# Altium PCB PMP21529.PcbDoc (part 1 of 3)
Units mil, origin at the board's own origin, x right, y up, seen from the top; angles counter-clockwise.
Board outline 4400 x 2200 mil, 4 copper layers (Top Layer, Signal Layer 1, Signal Layer 2, Bottom Layer), stack 41.2 mil thick; 196 components, 92 nets, 502 pads, 268 vias.
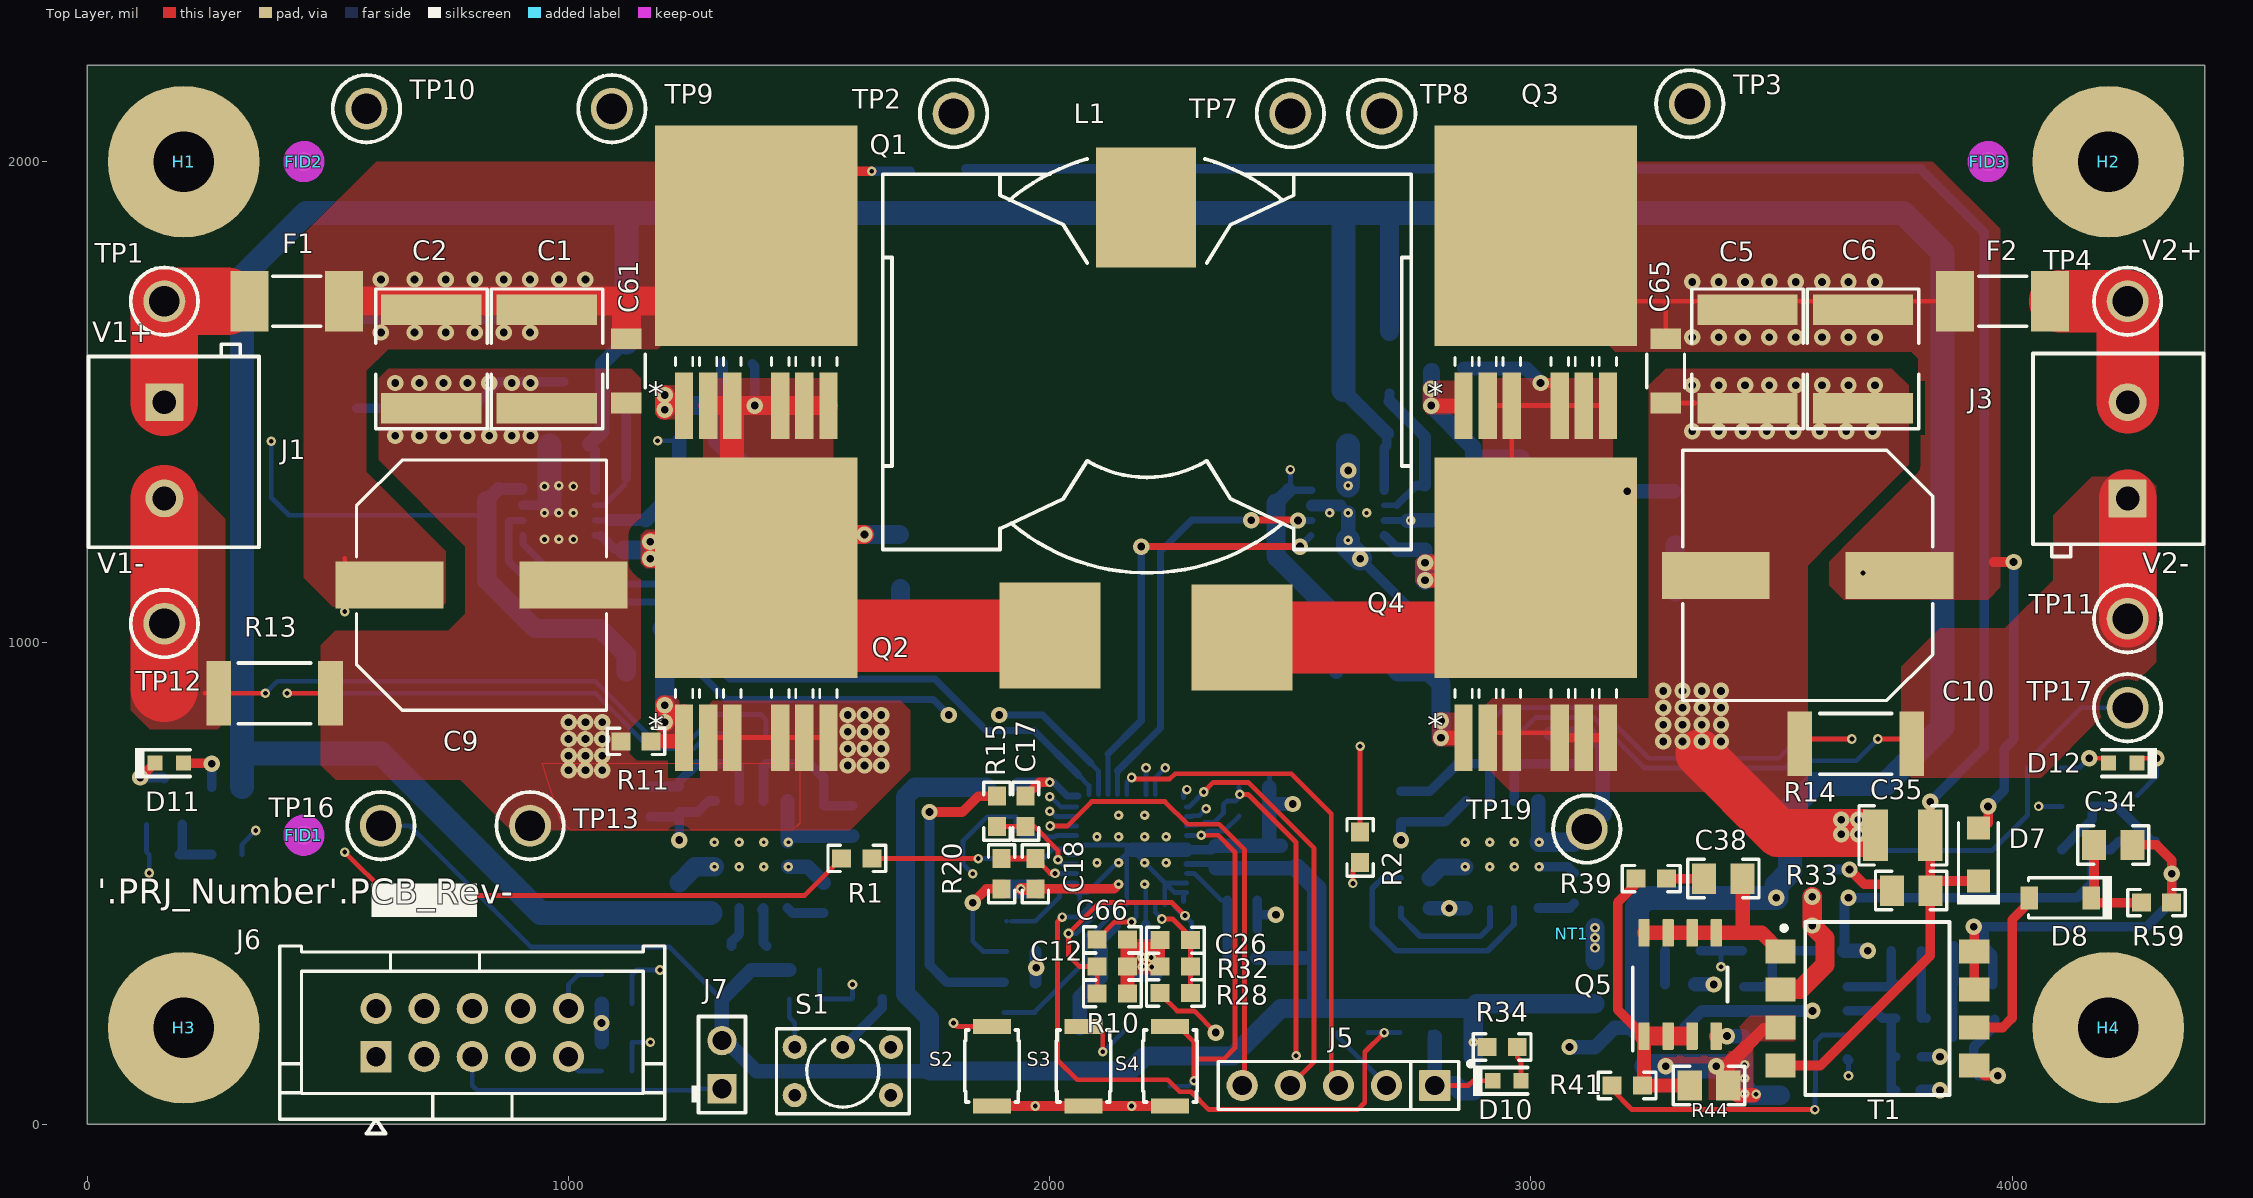
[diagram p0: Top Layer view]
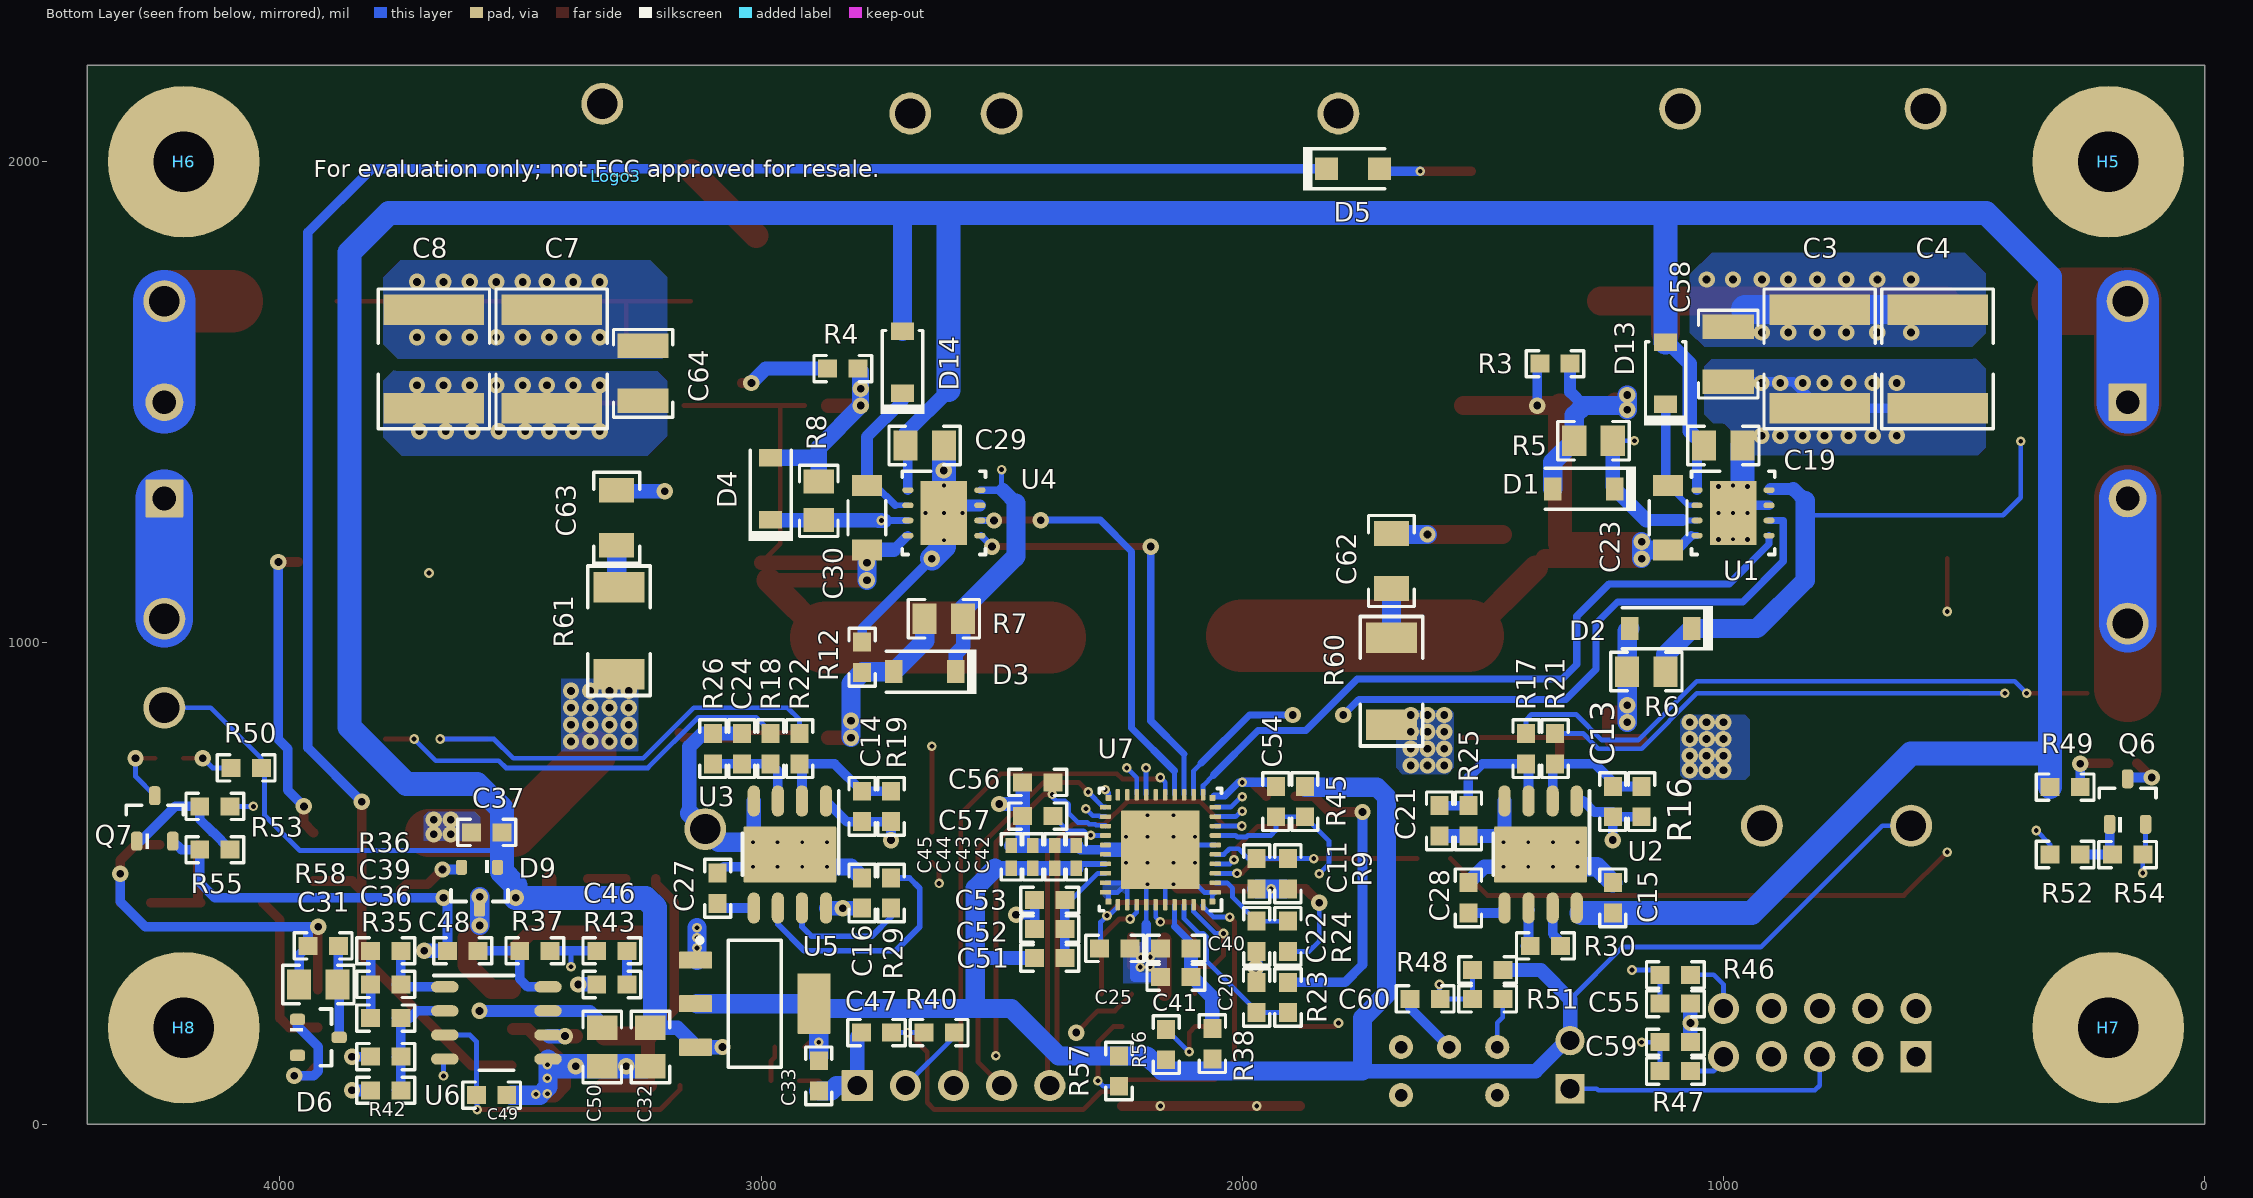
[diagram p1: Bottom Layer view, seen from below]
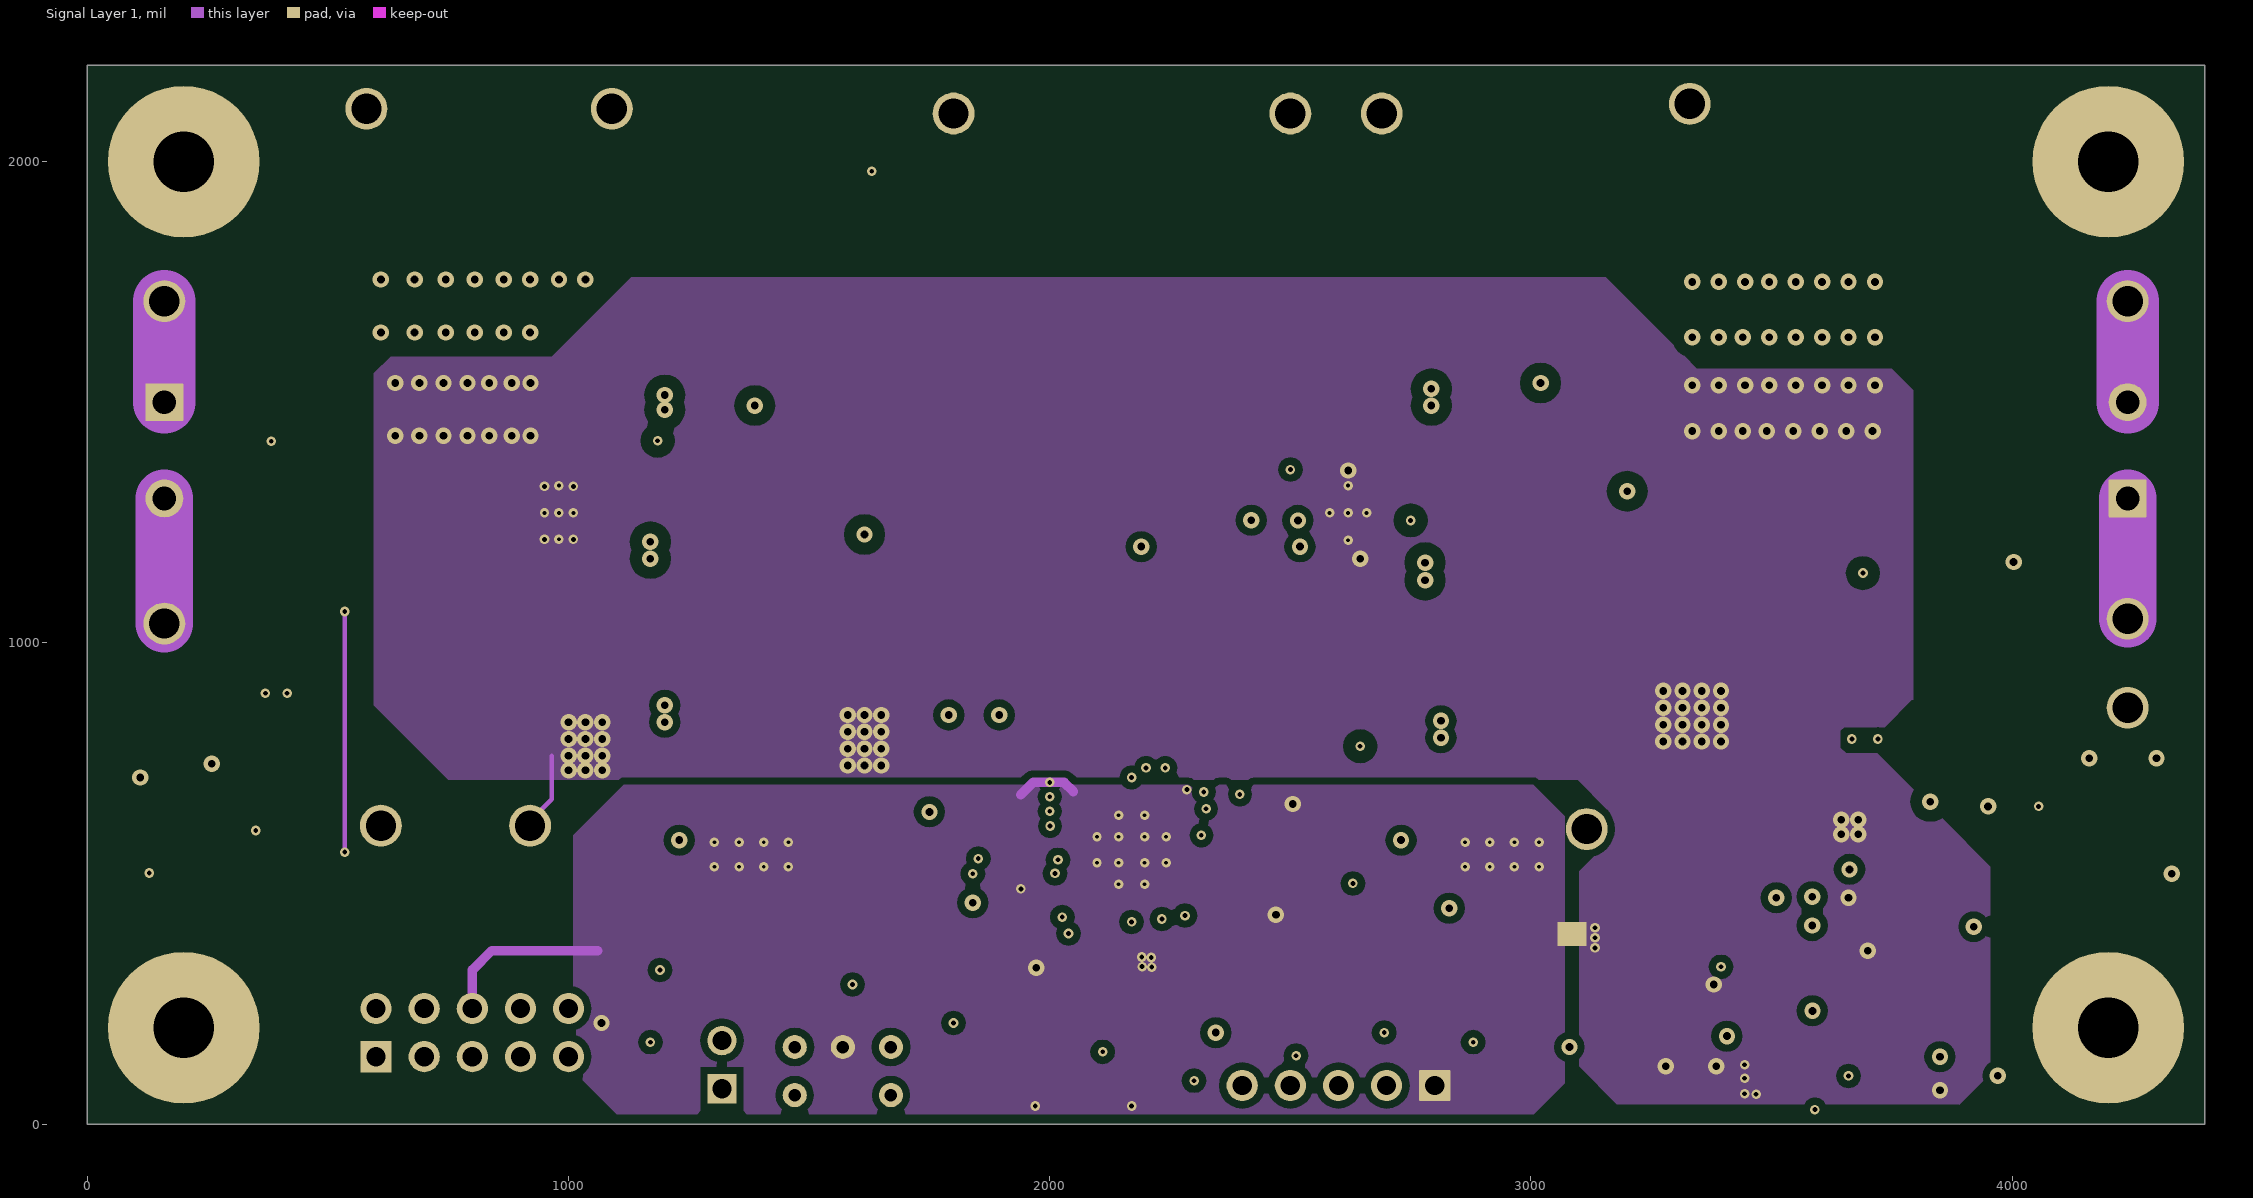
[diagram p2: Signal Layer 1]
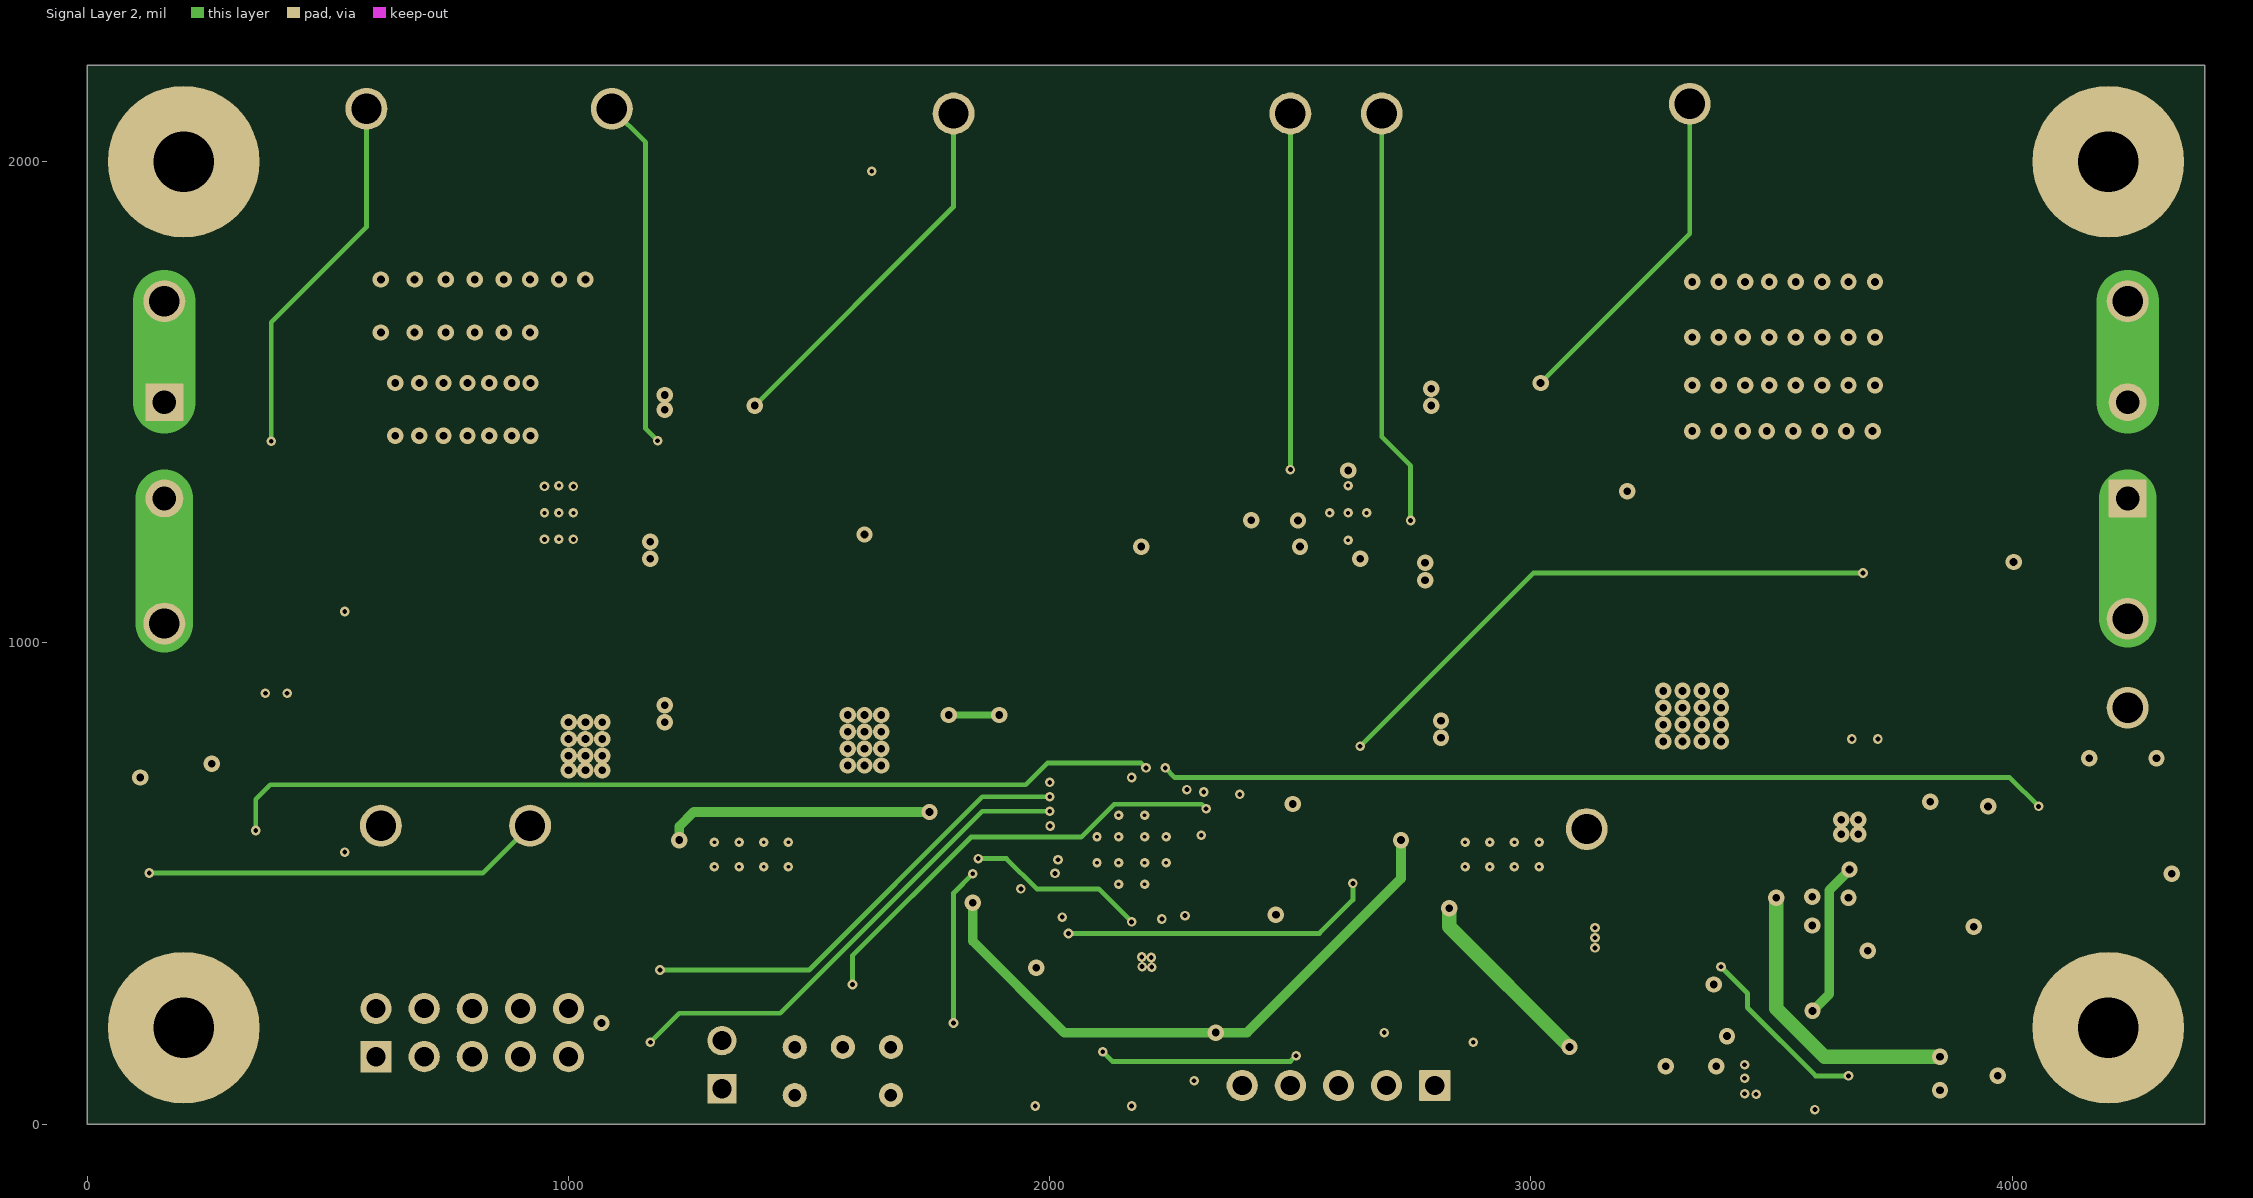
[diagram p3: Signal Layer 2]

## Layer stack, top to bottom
Top Solder: solder mask 0.4, Solder Resist, Dk 3.5
Top Layer: signal copper 2.8
Dielectric1: core 10, FR-4, Dk 4.8
Signal Layer 1: signal copper 2.8
Dielectric 2: core 10, FR-4, Dk 4.8
Signal Layer 2: signal copper 2.8
Dielectric 3: core 10, FR-4, Dk 4.8
Bottom Layer: signal copper 2.8
Bottom Solder: solder mask 0.4, Solder Resist, Dk 3.5

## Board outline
0,0 0,2200 4400,2200 4400,0

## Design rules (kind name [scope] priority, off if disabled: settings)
AcuteAngle [All] p1: minimum=4.50000000000000E+0001 checktracksonly=FALSE
AssemblyTestPointUsage [All] p1: valid=2
BoardOutlineClearance BoardOutlineClearance_MountingHoles [OnCopper and InComponentClass('Mounting Holes')] p1: gap=20 ignorepadtopadclearanceinfootprint=FALSE
BoardOutlineClearance BoardOutlineClearance_Poly [OnCopper and IsPoly] p2: gap=20 ignorepadtopadclearanceinfootprint=FALSE
BoardOutlineClearance [OnCopper and Not InComponentClass('Logo') and not InComponentClass('FiducialMark') and not InRegion(1000,500,4000,800) and not InPoly] p3: gap=20 ignorepadtopadclearanceinfootprint=FALSE
Clearance "1. HVvPGND Objs on Multilayer" [InNetClass('HV') And OnMultiLayer vs Not InNetClass('HV') And OnMultiLayer] p1: gap=25 ignorepadtopadclearanceinfootprint=FALSE except(0: Arc-Text Track-Text SMDPad-Text THPad-Text Via-Text Fill-Text Poly-Text Region-Text Text-Text)
Clearance "2a. HVvPGND Objs on Top" [InNetClass('HV') And OnTopLayer vs Not InNetClass('HV') And (OnTopLayer Or OnMultiLayer)] p2: gap=25 ignorepadtopadclearanceinfootprint=FALSE except(0: Arc-Text Track-Text SMDPad-Text THPad-Text Via-Text Fill-Text Poly-Text Region-Text Text-Text)
Clearance "2b. HVvPGND Objs on Bottom" [InNetClass('HV') And OnBottomLayer vs Not InNetClass('HV') And (OnBottomLayer Or OnMultiLayer)] p3: gap=25 ignorepadtopadclearanceinfootprint=FALSE except(0: Arc-Text Track-Text SMDPad-Text THPad-Text Via-Text Fill-Text Poly-Text Region-Text Text-Text)
Clearance "3a. HVvPGND Objs on Top" [Not InNetClass('HV') And OnTopLayer vs InNetClass('HV') And (OnTopLayer Or OnMultiLayer)] p4: gap=25 ignorepadtopadclearanceinfootprint=FALSE except(0: Arc-Text Track-Text SMDPad-Text THPad-Text Via-Text Fill-Text Poly-Text Region-Text Text-Text)
Clearance "3b. HVvPGND Objs on Bottom_1" [Not InNetClass('HV') And OnBottomLayer vs InNetClass('HV') And (OnBottomLayer Or OnMultiLayer)] p5: gap=25 ignorepadtopadclearanceinfootprint=FALSE except(0: Arc-Text Track-Text SMDPad-Text THPad-Text Via-Text Fill-Text Poly-Text Region-Text Text-Text)
Clearance "4. HVvPGND  Objs on Mid" [InNetClass('HV') And OnMid vs Not InNetClass('HV') And (OnMid Or OnMultiLayer)] p6: gap=25 ignorepadtopadclearanceinfootprint=FALSE except(0: Arc-Text Track-Text SMDPad-Text THPad-Text Via-Text Fill-Text Poly-Text Region-Text Text-Text)
Clearance "5. HVvPGND Objs on Mid" [Not InNetClass('HV') And OnMid vs InNetClass('HV') And (OnMid Or OnMultiLayer)] p7: gap=25 ignorepadtopadclearanceinfootprint=FALSE except(0: Arc-Text Track-Text SMDPad-Text THPad-Text Via-Text Fill-Text Poly-Text Region-Text Text-Text)
Clearance Clearance_Keepouts [((IsTrack Or IsArc) And Not InPoly) And IsFree and IsKeepOut vs ((IsTrack Or IsArc) And Not InPoly) And IsFree and IsKeepOut] p8: gap=0 ignorepadtopadclearanceinfootprint=FALSE
Clearance Clearance_Poly [InPolygon] p9: gap=15 ignorepadtopadclearanceinfootprint=FALSE except(0: Arc-Text Arc-Hole Track-Text Track-Hole SMDPad-Text SMDPad-Hole THPad-Text THPad-Hole Via-Text Via-Hole Fill-Text Fill-Hole Poly-Text Poly-Hole Region-Text Region-Hole Text-Text Text-Hole)
Clearance Clearance_FiducialMark [IsKeepOut and InComponentClass('FiducialMark') vs IsPad and InComponentClass('FiducialMark')] p10: gap=0 ignorepadtopadclearanceinfootprint=FALSE
Clearance [All] p11: gap=7.87 ignorepadtopadclearanceinfootprint=FALSE except(0: Arc-Text Arc-Hole Track-Text Track-Hole SMDPad-Text SMDPad-Hole THPad-Text THPad-Hole Via-Text Via-Hole Fill-Text Fill-Hole Poly-Text Poly-Hole Region-Text Region-Hole Text-Text Text-Hole)
ComponentClearance ComponentClearance_MountingHoles_FiducialMarks [InComponentClass('Mounting Holes') vs InComponentClass('FiducialMark')] p1: gap=50 collisioncheckmode=3 verticalgap=10 showdistances=FALSE
ComponentClearance ComponentClearance_Shunt [InComponentClass('Header') vs InComponentClass('Shunt')] p2: gap=0 collisioncheckmode=3 verticalgap=0 showdistances=FALSE
ComponentClearance ComponentClearance_Logo [InComponentClass('Logo')] p3: gap=0 collisioncheckmode=3 verticalgap=10 showdistances=FALSE
ComponentClearance ComponentClearance_ScrewToNut [(HasFootprint('NY PMS 440 0025 PH')) vs (HasFootprint('Keystone_1902C'))] p4: gap=5 collisioncheckmode=3 verticalgap=10 showdistances=FALSE
ComponentClearance ComponentClearance_MountingHoles [InComponentClass('Mounting Holes')] p5: gap=100 collisioncheckmode=3 verticalgap=100000 showdistances=FALSE
ComponentClearance ComponentClearance_SmallPassives [HasFootprint('0201*') or HasFootprint('0402*') or HasFootprint('0508') or HasFootprint('0603*') or HasFootprint('0612') or HasFootprint('0805*') or HasFootprint('0815*') or HasFootprint('0830*') or HasFootprint('1206*') or HasFootprint('1210*') or HasFootprint('1808*') or HasFootprint('1812*') or HasFootprint('1825*') or HasFootprint('2010*') or HasFootprint('2220*') or HasFootprint('2225*') or HasFootprint('2512*') or HasFootprint('2728*') or HasFootprint('3518*') vs HasFootprint('0201*') or HasFootprint('0402*') or HasFootprint('0508') or HasFootprint('0603*') or HasFootprint('0612') or HasFootprint('0805*') or HasFootprint('0815*') or HasFootprint('0830*') or HasFootprint('1206*') or HasFootprint('1210*') or HasFootprint('1808*') or HasFootprint('1812*') or HasFootprint('1825*') or HasFootprint('2010*') or HasFootprint('2220*') or HasFootprint('2225*') or HasFootprint('2512*') or HasFootprint('2728*') or HasFootprint('3518*')] p6: gap=14.96 collisioncheckmode=3 verticalgap=10 showdistances=FALSE
ComponentClearance ComponentClearance_THtoSMT [IsThruComponent vs IsSMTComponent] p7: gap=30 collisioncheckmode=3 verticalgap=30 showdistances=FALSE
ComponentClearance ComponentClearance_THtoTH [IsThruComponent vs IsThruComponent] p8: gap=30 collisioncheckmode=3 verticalgap=30 showdistances=FALSE
ComponentClearance [All] p9: gap=15 collisioncheckmode=3 verticalgap=10 showdistances=FALSE
DiffPairsRouting [All] p1: maxlimit=100 minlimit=10 mostfreqgap=10 toplayer_minwidth=15 toplayer_maxwidth=15 toplayer_prefwidth=15 midlayer1_minwidth=15 midlayer1_maxwidth=15 midlayer1_prefwidth=15 midlayer2_minwidth=15 midlayer2_maxwidth=15 midlayer2_prefwidth=15 bottomlayer_minwidth=15 bottomlayer_maxwidth=15 bottomlayer_prefwidth=15 maxuncoupledlength=1000
FabricationTestPointUsage TestPointUsage [All] p1: valid=2 allowmultiple=FALSE
FabricationTestpoint Testpoint [All] p1: side=3 testpointundercomponent=TRUE minsize=40 maxsize=100 preferedsize=60 minholesize=0 maxholesize=40 preferedholesize=32 testpointgrid=1 allowsidetop=TRUE allowsidebottom=TRUE usegrid=TRUE gridtolerance=0.01
FanoutControl Fanout_LCC [IsLCC] p1: bgadir=Out bgaviamode=Centered fanoutstyle=Auto fanoutdirection=Alternating viagrid=1 // Fanout_LCC (Default Rule)
FanoutControl Fanout_BGA [IsBGA] p2: bgadir=Out bgaviamode=Centered fanoutstyle=Auto fanoutdirection=Alternating viagrid=1 // Fanout_BGA (Default Rule)
FanoutControl Fanout_Default [All] p4: bgadir=Out bgaviamode=Centered fanoutstyle=Auto fanoutdirection=Alternating viagrid=1 // Fanout_Default (Default Rule)
FanoutControl Fanout_Small [(CompPinCount < 5)] p5: bgadir=Out bgaviamode=Centered fanoutstyle=Auto fanoutdirection=OutThenIn viagrid=1 // Fanout_Small (Default Rule)
HoleSize [All] p1: absolutevalues=TRUE maxlimit=251 minlimit=7.87 maxpercent=80.000 minpercent=20.000
MinimumAnnularRing MinimumAnnularRing_ThermalPadVias [IsVia and InAnyComponent] p1: minimumring=5.91
MinimumAnnularRing [All] p2: minimumring=5
MinimumSolderMaskSliver MinimumSolderMaskSliver_Logo [InComponentClass('Logo') vs InComponentClass('Logo')] p1: minsoldermaskwidth=0.7
MinimumSolderMaskSliver [All] p2: minsoldermaskwidth=3.94
PlaneConnect [All] p1: planeconnectstyle=Relief reliefexpansion=10 reliefentries=4 reliefconductorwidth=10 reliefairgap=10
PolygonConnect PolygonConnect_63 [All vs IsNamedPolygon('BOTTOM_LAYER_PGND_P092')] p1: connectstyle=Direct reliefconductorwidth=10 reliefentries=4 polygonreliefangle="90 Angle" airgapwidth=10
PolygonConnect PolygonConnect_62 [All vs IsNamedPolygon('TOP_LAYER_NETJ1_2_P116')] p2: connectstyle=Direct reliefconductorwidth=10 reliefentries=4 polygonreliefangle="90 Angle" airgapwidth=10
PolygonConnect PolygonConnect_61 [All vs IsNamedPolygon('TOP_LAYER_NETJ3_1_P114')] p3: connectstyle=Direct reliefconductorwidth=10 reliefentries=4 polygonreliefangle="90 Angle" airgapwidth=10
PolygonConnect PolygonConnect_60 [All vs IsNamedPolygon('TOP_LAYER_V2+_P112')] p4: connectstyle=Direct reliefconductorwidth=10 reliefentries=4 polygonreliefangle="90 Angle" airgapwidth=10
PolygonConnect PolygonConnect_59 [All vs IsNamedPolygon('TOP_LAYER_PGND_P110')] p5: connectstyle=Direct reliefconductorwidth=10 reliefentries=4 polygonreliefangle="90 Angle" airgapwidth=10
PolygonConnect PolygonConnect_58 [All vs IsNamedPolygon('BOTTOM_LAYER_PGND_P072')] p6: connectstyle=Direct reliefconductorwidth=10 reliefentries=4 polygonreliefangle="90 Angle" airgapwidth=10
PolygonConnect PolygonConnect_57 [All vs IsNamedPolygon('TOP_LAYER_V1+_P108')] p7: connectstyle=Direct reliefconductorwidth=10 reliefentries=4 polygonreliefangle="90 Angle" airgapwidth=10
PolygonConnect PolygonConnect_56 [All vs IsNamedPolygon('TOP_LAYER_PGND_P106')] p8: connectstyle=Direct reliefconductorwidth=10 reliefentries=4 polygonreliefangle="90 Angle" airgapwidth=10
PolygonConnect PolygonConnect_55 [All vs IsNamedPolygon('TOP_LAYER_AGND_P104')] p9: connectstyle=Direct reliefconductorwidth=10 reliefentries=4 polygonreliefangle="90 Angle" airgapwidth=10
PolygonConnect PolygonConnect_54 [All vs IsNamedPolygon('BOTTOM_LAYER_AGND_P102')] p10: connectstyle=Direct reliefconductorwidth=10 reliefentries=4 polygonreliefangle="90 Angle" airgapwidth=10
PolygonConnect PolygonConnect_53 [All vs IsNamedPolygon('BOTTOM_LAYER_AGND_P100')] p11: connectstyle=Direct reliefconductorwidth=10 reliefentries=4 polygonreliefangle="90 Angle" airgapwidth=10
PolygonConnect PolygonConnect_52 [All vs IsNamedPolygon('BOTTOM_LAYER_AGND_P098')] p12: connectstyle=Direct reliefconductorwidth=10 reliefentries=4 polygonreliefangle="90 Angle" airgapwidth=10
PolygonConnect PolygonConnect_51 [All vs IsNamedPolygon('BOTTOM_LAYER_PGND_P096')] p13: connectstyle=Direct reliefconductorwidth=10 reliefentries=4 polygonreliefangle="90 Angle" airgapwidth=10
PolygonConnect PolygonConnect_50 [All vs IsNamedPolygon('TOP_LAYER_PGND_P094')] p14: connectstyle=Direct reliefconductorwidth=10 reliefentries=4 polygonreliefangle="90 Angle" airgapwidth=10
PolygonConnect PolygonConnect_49 [All vs IsNamedPolygon('BOTTOM_LAYER_NETC5_2_P092')] p15: connectstyle=Direct reliefconductorwidth=10 reliefentries=4 polygonreliefangle="90 Angle" airgapwidth=10
PolygonConnect PolygonConnect_48 [All vs IsNamedPolygon('BOTTOM_LAYER_V2+_P090')] p16: connectstyle=Direct reliefconductorwidth=10 reliefentries=4 polygonreliefangle="90 Angle" airgapwidth=10
PolygonConnect PolygonConnect_47 [All vs IsNamedPolygon('TOP_LAYER_NETC5_2_P088')] p17: connectstyle=Direct reliefconductorwidth=10 reliefentries=4 polygonreliefangle="90 Angle" airgapwidth=10
PolygonConnect PolygonConnect_46 [All vs IsNamedPolygon('TOP_LAYER_V2+_P086')] p18: connectstyle=Direct reliefconductorwidth=10 reliefentries=4 polygonreliefangle="90 Angle" airgapwidth=10
PolygonConnect PolygonConnect_45 [All vs IsNamedPolygon('TOP_LAYER_PGND_P082')] p19: connectstyle=Direct reliefconductorwidth=10 reliefentries=4 polygonreliefangle="90 Angle" airgapwidth=10
PolygonConnect PolygonConnect_44 [All vs IsNamedPolygon('TOP_LAYER_NETC1_2_P080')] p20: connectstyle=Direct reliefconductorwidth=10 reliefentries=4 polygonreliefangle="90 Angle" airgapwidth=10
PolygonConnect PolygonConnect_43 [All vs IsNamedPolygon('TOP_LAYER_NETC1_2_P080')] p21: thpad.connectstyle=Relief thpad.reliefconductorwidth=10 thpad.reliefentries=4 thpad.polygonreliefangle="90 Angle" thpad.airgapwidth=10 smdpad.connectstyle=Direct smdpad.reliefconductorwidth=10 smdpad.reliefentries=4 smdpad.polygonreliefangle="90 Angle" smdpad.airgapwidth=10 via.connectstyle=Relief via.reliefconductorwidth=10 via.reliefentries=4 via.polygonreliefangle="90 Angle" via.airgapwidth=10
PolygonConnect PolygonConnect_42 [All vs IsNamedPolygon('BOTTOM_LAYER_PGND_P078')] p22: connectstyle=Direct reliefconductorwidth=10 reliefentries=4 polygonreliefangle="90 Angle" airgapwidth=10
PolygonConnect PolygonConnect_41 [All vs IsNamedPolygon('BOTTOM_LAYER_PGND_P076')] p23: connectstyle=Direct reliefconductorwidth=10 reliefentries=4 polygonreliefangle="90 Angle" airgapwidth=10
PolygonConnect PolygonConnect_40 [All vs IsNamedPolygon('TOP_LAYER_PGND_P074')] p24: connectstyle=Direct reliefconductorwidth=10 reliefentries=4 polygonreliefangle="90 Angle" airgapwidth=10
PolygonConnect PolygonConnect_39 [All vs IsNamedPolygon('BOTTOM_LAYER_NETC1_2_P072')] p25: connectstyle=Direct reliefconductorwidth=10 reliefentries=4 polygonreliefangle="90 Angle" airgapwidth=10
PolygonConnect PolygonConnect_38 [All vs IsNamedPolygon('BOTTOM_LAYER_V1+_P070')] p26: connectstyle=Direct reliefconductorwidth=10 reliefentries=4 polygonreliefangle="90 Angle" airgapwidth=10
PolygonConnect PolygonConnect_37 [All vs IsNamedPolygon('TOP_LAYER_NETC1_2_P068')] p27: connectstyle=Direct reliefconductorwidth=10 reliefentries=4 polygonreliefangle="90 Angle" airgapwidth=10
PolygonConnect PolygonConnect_36 [All vs IsNamedPolygon('TOP_LAYER_V1+_P064')] p28: connectstyle=Direct reliefconductorwidth=10 reliefentries=4 polygonreliefangle="90 Angle" airgapwidth=10
PolygonConnect PolygonConnect_35 [All vs IsNamedPolygon('TOP_LAYER_SW1_P062')] p29: connectstyle=Direct reliefconductorwidth=10 reliefentries=4 polygonreliefangle="90 Angle" airgapwidth=10
PolygonConnect PolygonConnect_34 [All vs IsNamedPolygon('TOP_LAYER_NETD2_2_P060')] p30: connectstyle=Direct reliefconductorwidth=10 reliefentries=4 polygonreliefangle="90 Angle" airgapwidth=10
PolygonConnect PolygonConnect_33 [All vs IsNamedPolygon('TOP_LAYER_NETD1_2_P056')] p31: connectstyle=Direct reliefconductorwidth=10 reliefentries=4 polygonreliefangle="90 Angle" airgapwidth=10
PolygonConnect PolygonConnect_32 [All vs IsNamedPolygon('SIGNAL_LAYER_1_PGND_P054')] p32: connectstyle=Direct reliefconductorwidth=10 reliefentries=4 polygonreliefangle="90 Angle" airgapwidth=10
PolygonConnect PolygonConnect_31 [All vs IsNamedPolygon('TOP_LAYER_NETC5_2_P050')] p33: connectstyle=Direct reliefconductorwidth=10 reliefentries=4 polygonreliefangle="90 Angle" airgapwidth=10
PolygonConnect PolygonConnect_30 [All vs IsNamedPolygon('TOP_LAYER_V2+_P048')] p34: connectstyle=Direct reliefconductorwidth=10 reliefentries=4 polygonreliefangle="90 Angle" airgapwidth=10
PolygonConnect PolygonConnect_29 [All vs IsNamedPolygon('TOP_LAYER_NETC1_2_P046')] p35: connectstyle=Direct reliefconductorwidth=10 reliefentries=4 polygonreliefangle="90 Angle" airgapwidth=10
PolygonConnect PolygonConnect_28 [All vs IsNamedPolygon('TOP_LAYER_PGND_P044')] p36: connectstyle=Direct reliefconductorwidth=10 reliefentries=4 polygonreliefangle="90 Angle" airgapwidth=10
PolygonConnect PolygonConnect_27 [All vs IsNamedPolygon('TOP_LAYER_V1+_P042')] p37: connectstyle=Direct reliefconductorwidth=10 reliefentries=4 polygonreliefangle="90 Angle" airgapwidth=10
PolygonConnect PolygonConnect_26 [All vs IsNamedPolygon('TOP_LAYER_NETD3_2_P040')] p38: connectstyle=Direct reliefconductorwidth=10 reliefentries=4 polygonreliefangle="90 Angle" airgapwidth=10
PolygonConnect PolygonConnect_25 [All vs IsNamedPolygon('TOP_LAYER_SW2_P036')] p39: connectstyle=Direct reliefconductorwidth=10 reliefentries=4 polygonreliefangle="90 Angle" airgapwidth=10
PolygonConnect PolygonConnect_24 [All vs IsNamedPolygon('TOP_LAYER_NETD4_2_P034')] p40: connectstyle=Direct reliefconductorwidth=10 reliefentries=4 polygonreliefangle="90 Angle" airgapwidth=10
PolygonConnect PolygonConnect_23 [All vs IsNamedPolygon('BOTTOM_LAYER_AGND_P032')] p41: thpad.connectstyle=Direct thpad.reliefconductorwidth=10 thpad.reliefentries=4 thpad.polygonreliefangle="90 Angle" thpad.airgapwidth=10 smdpad.connectstyle=Direct smdpad.reliefconductorwidth=10 smdpad.reliefentries=4 smdpad.polygonreliefangle="90 Angle" smdpad.airgapwidth=10 via.connectstyle=Relief via.reliefconductorwidth=10 via.reliefentries=4 via.polygonreliefangle="90 Angle" via.airgapwidth=10
PolygonConnect PolygonConnect_22 [All vs IsNamedPolygon('BOTTOM_LAYER_AGND_P032')] p42: connectstyle=Direct reliefconductorwidth=10 reliefentries=4 polygonreliefangle="90 Angle" airgapwidth=10
PolygonConnect PolygonConnect_21 [All vs IsNamedPolygon('BOTTOM_LAYER_AGND_P032')] p43: connectstyle=Direct reliefconductorwidth=10 reliefentries=4 polygonreliefangle="90 Angle" airgapwidth=10
PolygonConnect PolygonConnect_20 [All vs IsNamedPolygon('BOTTOM_LAYER_AGND_P030')] p44: connectstyle=Direct reliefconductorwidth=10 reliefentries=4 polygonreliefangle="90 Angle" airgapwidth=10
PolygonConnect PolygonConnect_19 [All vs IsNamedPolygon('BOTTOM_LAYER_AGND_P028')] p45: connectstyle=Direct reliefconductorwidth=10 reliefentries=4 polygonreliefangle="90 Angle" airgapwidth=10
PolygonConnect PolygonConnect_18 [All vs IsNamedPolygon('BOTTOM_LAYER_AGND_P028')] p46: connectstyle=Direct reliefconductorwidth=10 reliefentries=4 polygonreliefangle="90 Angle" airgapwidth=10
PolygonConnect PolygonConnect_17 [All vs IsNamedPolygon('BOTTOM_LAYER_AGND_P028')] p47: connectstyle=Direct reliefconductorwidth=10 reliefentries=4 polygonreliefangle="90 Angle" airgapwidth=10
PolygonConnect PolygonConnect_16 [All vs IsNamedPolygon('BOTTOM_LAYER_AGND_P028')] p48: connectstyle=Direct reliefconductorwidth=10 reliefentries=4 polygonreliefangle="90 Angle" airgapwidth=10
PolygonConnect PolygonConnect_15 [All vs IsNamedPolygon('BOTTOM_LAYER_AGND_P028')] p49: thpad.connectstyle=Direct thpad.reliefconductorwidth=10 thpad.reliefentries=4 thpad.polygonreliefangle="90 Angle" thpad.airgapwidth=10 smdpad.connectstyle=Direct smdpad.reliefconductorwidth=10 smdpad.reliefentries=4 smdpad.polygonreliefangle="90 Angle" smdpad.airgapwidth=10 via.connectstyle=Relief via.reliefconductorwidth=10 via.reliefentries=4 via.polygonreliefangle="90 Angle" via.airgapwidth=10
PolygonConnect PolygonConnect_14 [All vs IsNamedPolygon('BOTTOM_LAYER_AGND_P028')] p50: connectstyle=Direct reliefconductorwidth=10 reliefentries=4 polygonreliefangle="90 Angle" airgapwidth=10
PolygonConnect PolygonConnect_13 [All vs IsNamedPolygon('BOTTOM_LAYER_AGND_P028')] p51: connectstyle=Direct reliefconductorwidth=10 reliefentries=4 polygonreliefangle="90 Angle" airgapwidth=10
PolygonConnect PolygonConnect_12 [All vs IsNamedPolygon('BOTTOM_LAYER_AGND_P028')] p52: connectstyle=Direct reliefconductorwidth=10 reliefentries=4 polygonreliefangle="90 Angle" airgapwidth=10
PolygonConnect PolygonConnect_11 [All vs IsNamedPolygon('SIGNAL_LAYER_1_PGND_P022')] p53: connectstyle=Direct reliefconductorwidth=10 reliefentries=4 polygonreliefangle="90 Angle" airgapwidth=10
PolygonConnect PolygonConnect_10 [All vs IsNamedPolygon('BOTTOM_LAYER_PGND_P020')] p54: connectstyle=Direct reliefconductorwidth=10 reliefentries=4 polygonreliefangle="90 Angle" airgapwidth=10
PolygonConnect PolygonConnect_9 [All vs IsNamedPolygon('BOTTOM_LAYER_PGND_P018')] p55: connectstyle=Direct reliefconductorwidth=10 reliefentries=4 polygonreliefangle="90 Angle" airgapwidth=10
PolygonConnect PolygonConnect_8 [All vs IsNamedPolygon('SIGNAL_LAYER_1_AGND_P002')] p56: connectstyle=Direct reliefconductorwidth=10 reliefentries=4 polygonreliefangle="90 Angle" airgapwidth=10
PolygonConnect PolygonConnect_7 [All vs IsNamedPolygon('SIGNAL_LAYER_1_PGND_P000')] p57: connectstyle=Direct reliefconductorwidth=10 reliefentries=4 polygonreliefangle="90 Angle" airgapwidth=10
PolygonConnect PolygonConnect_6 [All vs IsNamedPolygon('TOP_LAYER_PGND_P016')] p58: connectstyle=Direct reliefconductorwidth=10 reliefentries=4 polygonreliefangle="90 Angle" airgapwidth=10
PolygonConnect PolygonConnect_5 [All vs IsNamedPolygon('TOP_LAYER_PGND_P012')] p59: connectstyle=Direct reliefconductorwidth=10 reliefentries=4 polygonreliefangle="90 Angle" airgapwidth=10
PolygonConnect PolygonConnect_4 [All vs IsNamedPolygon('TOP_LAYER_PGND_P010')] p60: connectstyle=Direct reliefconductorwidth=10 reliefentries=4 polygonreliefangle="90 Angle" airgapwidth=10
PolygonConnect PolygonConnect_3 [All vs IsNamedPolygon('SIGNAL_LAYER_1_PGND_P004')] p61: connectstyle=Direct reliefconductorwidth=10 reliefentries=4 polygonreliefangle="90 Angle" airgapwidth=10
PolygonConnect PolygonConnect_2 [All vs IsNamedPolygon('TOP_LAYER_SW1_P008')] p62: connectstyle=Direct reliefconductorwidth=10 reliefentries=4 polygonreliefangle="90 Angle" airgapwidth=10
PolygonConnect PolygonConnect_1 [All vs IsNamedPolygon('TOP_LAYER_SW2_P006')] p63: connectstyle=Direct reliefconductorwidth=10 reliefentries=4 polygonreliefangle="90 Angle" airgapwidth=10
PolygonConnect [All] p64: connectstyle=Relief reliefconductorwidth=10 reliefentries=4 polygonreliefangle="90 Angle" airgapwidth=10
RoutingVias ThermalPadVias [IsVia and InAnyComponent] p1: holewidth=7.87 width=19.68 viastyle="Through Hole" minholewidth=7.87 minwidth=19.68 maxholewidth=12.99 maxwidth=23.62
RoutingVias [All] p2: holewidth=16 width=34 viastyle="Through Hole" minholewidth=7.87 minwidth=20 maxholewidth=40 maxwidth=65
SilkToBoardRegionClearance [Not ((IsComment or IsDesignator) And (Hide <> 'False')) and not InRegion(1000,500,4000,800)] p1:
SilkToSilkClearance SilkToSilkClearance_Pb-FreeLogo [(HasFootprint('Pb-Free_Overlay_Medium') OR HasFootprint('Pb-Free_Overlay_Small')) vs (HasFootprint('Pb-Free_Overlay_Medium') OR HasFootprint('Pb-Free_Overlay_Small'))] p1: silktosilkclearance=0
SilkToSilkClearance [All] p2: silktosilkclearance=1
SilkToSolderMaskClearance SilkToComponentPadClearance [(IsPad or IsFill or IsRegion) and InAnycomponent] p1: minsilkscreentomaskgap=5 clearancetoexposedcopper=TRUE
SilkToSolderMaskClearance "Silk to Solder Mask Opening" [All] p2: minsilkscreentomaskgap=1 clearancetoexposedcopper=FALSE
SolderMaskExpansion [All] p1: expansion=1.97
Width [All] p1: maxlimit=200 minlimit=6 preferedwidth=10 checkconnectedcopper=TRUE
15 further rules are at their usual default settings.

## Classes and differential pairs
component class AssemblyNote: ZZ2 ZZ3 ZZ4
component class FiducialMark: FID1 FID2 FID3
component class PMP21529_Hardware: FID1 FID2 FID3 H1 H2 H3 H4 H5 H6 H7 H8 Logo3 ZZ2 ZZ3 ZZ4
component class "Mounting Holes": H1 H2 H3 H4
component class Header: J5
component class PMP21529_Sheet1: C1 C2 C3 C4 C5 C6 C7 C8 C9 C10 C13 C14 C15 C16 C17 C18 C19 C20 C21 C22 C23 C24 C26 C27 C28 C29 C30 C58 C61 C62 C63 C64 C65 D1 D2 D3 D4 D13 D14 F1 F2 J1 J3 L1 Q1 Q2 Q3 Q4 R3 R4 R5 R6 R7 R8 R11 R12 R13 R14 R15 R16 R17 R18 R19 R20 R21 R22 R23 R24 R25 R26 R28 R29 R30 R32 R60 R61 TP1 TP2 TP3 TP4 TP7 TP8 TP9 TP10 TP11 TP12 TP13 U1 U2 U3 U4
component class PMP21529_Sheet2: C11 C12 C25 C31 C32 C33 C34 C35 C36 C37 C38 C39 C40 C41 C42 C43 C44 C45 C46 C47 C48 C49 C50 C51 C52 C53 C54 C55 C56 C57 C59 C60 C66 D5 D6 D7 D8 D9 D10 D11 D12 J5 J6 J7 NT1 Q5 Q6 Q7 R1 R2 R9 R10 R33 R34 R35 R36 R37 R38 R39 R40 R41 R42 R43 R44 R45 R46 R47 R48 R49 R50 R51 R52 R53 R54 R55 R56 R57 R58 R59 S1 S2 S3 S4 T1 TP16 TP17 TP19 U5 U6 U7
net class HV: H1 H2 NetC35_1 NetC38_1 NetD1_2 NetD4_2 NetF2_1 SW1 SW2 V1+ V2+

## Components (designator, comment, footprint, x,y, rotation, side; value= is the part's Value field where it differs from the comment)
C1 "22201C106MAT2A" 2220_280 955,1590 r270 top value=10uF
C2 "22201C106MAT2A" 2220_280 715,1590 r270 top value=10uF
C3 "22201C106MAT2A" 2220_280 800,1590 r270 bottom value=10uF
C4 "22201C106MAT2A" 2220_280 555,1590 r270 bottom value=10uF
C5 "22201C106MAT2A" 2220_280 3450,1590 r270 top value=10uF
C6 "22201C106MAT2A" 2220_280 3690,1590 r270 top value=10uF
C7 "22201C106MAT2A" 2220_280 3435,1590 r270 bottom value=10uF
C8 "22201C106MAT2A" 2220_280 3680,1590 r270 bottom value=10uF
C9 "EMVA101ATR101MKE0S" CAPSMT_62_KE0 819,1120 r0 top value=100uF
C10 "EMVA101ATR101MKE0S" CAPSMT_62_KE0 3575,1140 r180 top value=100uF
C11 "GRM188R71E682KA01D" 0603 1970,520 r270 bottom value=6800pF
C12 "GRM188R71E682KA01D" 0603 2130,327 r0 top value=6800pF
C13 "Capacitor" 0603 1230,670 r270 bottom value=22pF
C14 "Capacitor" 0603 2790,660 r270 bottom value=22pF
C15 "Capacitor" 0603 1230,470 r90 bottom value=0.1uF
C16 "Capacitor" 0603 2790,480 r90 bottom value=0.1uF
C17 "Capacitor" 0603 1950,650 r90 top value=330pF
C18 "Capacitor" 0603 1970,520 r270 top value=330pF
C19 "GRM21BR71C475KA73L" 0805_HV 1000,1410 r180 bottom value=4.7uF
C20 "Capacitor" 0603 1970,263 r90 bottom value=2.2uF
C21 "Capacitor" 0603 1590,630 r270 bottom value=22pF
C22 "Capacitor" 0603 1970,390 r270 bottom value=2.2uF
C23 "C3216X7S2A225K160AB" 1206_180 1115,1260 r270 bottom value=2.2uF
C24 "Capacitor" 0603 3040,780 r90 bottom value=22pF
C25 "C0603C221K5RACTU" 0603 2265,365 r180 bottom value=220pF
C26 "Capacitor" 0603 2261,382 r180 top value=0.01uF
C27 "Capacitor" 0603 3090,490 r90 bottom value=22pF
C28 "Capacitor" 0603 1530,470 r90 bottom value=22pF
C29 "GRM21BR71C475KA73L" 0805_HV 2660,1410 r180 bottom value=4.7uF
C30 "C3216X7S2A225K160AB" 1206_180 2780,1260 r270 bottom value=2.2uF
C31 "Capacitor" 0805_HV 3920,290 r0 bottom value=2.2uF
C32 "Capacitor" 0805_HV 3230,160 r270 bottom value=10uF
C33 "Capacitor" 0603 2880,100 r270 bottom value=10uF
C34 "Capacitor" 0805_HV 4210,580 r0 top value=2.2uF
C35 "GRM32ER72A225KA35L" 1210_270 3773,600 r180 top value=2.2uF
C36 "Capacitor" 0603 3780,220 r0 bottom value=0.01uF
C37 "EMK107B7105KA-T" 0603 3570,606 r0 bottom value=1uF
C38 "Capacitor" 0805_HV 3400,510 r180 top value=47pF
C39 "Capacitor" 0603 3780,290 r180 bottom value=47pF
C40 "Capacitor" 0603 2138,365 r0 bottom value=0.01uF
C41 "Capacitor" 0603 2138,305 r0 bottom value=1uF
C42 "GRM155R71E104KE14D" 0402 2345,555 r90 bottom value=0.1uF
C43 "GRM155R71E104KE14D" 0402 2390,555 r90 bottom value=0.1uF
C44 "GRM155R71E104KE14D" 0402 2435,555 r90 bottom value=0.1uF
C45 "GRM155R70J105KA12D" 0402 2480,555 r90 bottom value=1uF
C46 "Capacitor" 0603 3310,360 r0 bottom value=330pF
C47 "Capacitor" 0603 2760,190 r0 bottom value=0.01uF
C48 "Capacitor" 0603 3620,360 r0 bottom value=0.1uF
C49 "Capacitor" 0603 3560,60 r180 bottom value=220pF
C50 "Capacitor" 0805_HV 3330,160 r270 bottom value=4.7uF
C51 "Capacitor" 0603 2400,345 r0 bottom value=2.2uF
C52 "EMK107B7105KA-T" 0603 2400,405 r0 bottom value=1uF
C53 "C0603H103J3GACTU" 0603 2400,465 r0 bottom value=0.01uF
C54 "EMK107BB7225MA-T" 0603 1930,670 r90 bottom value=2.2uF
C55 "Capacitor" 0603 1100,250 r180 bottom value=33pF
C56 "EMK107BB7225MA-T" 0603 2425,710 r0 bottom value=2.2uF
C57 "EMK107BB7225MA-T" 0603 2425,640 r0 bottom value=2.2uF
C58 "GRM32DC72A475KE01L" 1210_220 990,1600 r270 bottom value=4.7uF
C59 "Capacitor" 0603 1100,170 r180 bottom value=33pF
C60 "Capacitor" 0603 1620,260 r0 bottom value=0.01uF
C61 "C3216X7R2A105K160AA" 1206_180 1120,1565 r270 top value=1uF
C62 "GRM3195C2A562JA01D" 1206 1690,1170 r270 bottom value=5600pF
C63 "GRM3195C2A562JA01D" 1206 3300,1260 r270 bottom value=5600pF
C64 "GRM32DC72A475KE01L" 1210_220 3245,1560 r270 bottom value=4.7uF
C65 "C3216X7R2A105K160AA" 1206_180 3280,1565 r270 top value=1uF
C66 "C0603C221K5RACTU" 0603 2130,383 r0 top value=220pF
D1 "MBR0540T1G" SOD-123 1290,1320 r0 bottom value=40V
D2 "MBR0540T1G" SOD-123 1130,1030 r0 bottom value=40V
D3 "MBR0540T1G" SOD-123 2660,940 r0 bottom value=40V
D4 "MBR0540T1G" SOD-123 2980,1320 r90 bottom value=40V
D5 "PMEG10010ELRX" SOD-123W 1770,1985 r180 bottom value=100V
D6 "DIODE_A1C3" SOT-23L 3920,180 r180 bottom value=100V
D7 "PMEG10010ELRX" SOD-123W 3930,560 r90 top value=100V
D8 "MBR140SFT1G" SOD-123FL 4100,470 r180 top value=40V
D9 "DIODE_A3C1_A3C2" SOT-23L 3585,490 r270 bottom value=70V
D10 "LTST-C190GKT" LED_LTST-C190 2950,90 r180 top value=Green
D11 "LTST-C190GKT" LED_LTST-C190 170,750 r180 top value=Green
D12 "LTST-C190GKT" LED_LTST-C190 4230,750 r0 top value=Green
D13 "MBR1H100SFT3G" SOD-123FL 1120,1560 r90 bottom value=100V
D14 "MBR1H100SFT3G" SOD-123FL 2706,1583 r90 bottom value=100V
F1 "SSQ 15" FUSE_SSQ 435,1710 r180 top
F2 "SSQ 15" FUSE_SSQ 3980,1710 r180 top
FID1 "Fiducial" Fiducial10-20 450,600 r0 top
FID2 "Fiducial" Fiducial10-20 450,2000 r0 top
FID3 "Fiducial" Fiducial10-20 3950,2000 r0 top
H1 "NY PMS 440 0025 PH" "NY PMS 440 0025 PH" 200,2000 r0 top locked
H2 "NY PMS 440 0025 PH" "NY PMS 440 0025 PH" 4200,2000 r0 top locked
H3 "NY PMS 440 0025 PH" "NY PMS 440 0025 PH" 200,200 r0 top locked
H4 "NY PMS 440 0025 PH" "NY PMS 440 0025 PH" 4200,200 r0 top locked
H5 "1902C" Keystone_1902C 200,2000 r180 bottom locked
H6 "1902C" Keystone_1902C 4200,2000 r180 bottom locked
H7 "1902C" Keystone_1902C 200,200 r180 bottom locked
H8 "1902C" Keystone_1902C 4200,200 r180 bottom locked
J1 "Receptacle_2x1" On-Shore_ED120_2DS 160,1400 r270 top
J3 "Receptacle_2x1" On-Shore_ED120_2DS 4240,1400 r90 top
J5 "HTSW-105-07-G-S" Samtec_HTSW-105-07-G-S 2600,80 r180 top
J6 "Header_5x2" CONN_5103308-1 800,190 r0 top
J7 "HTSW-102-09-G-S" Samtec_HTSW-102-09-x-S 1318.77,123.39 r90 top
L1 "SER2918H-153KL" SER2918H 2200,1580 r90 top value=15uH
Logo3 "FCC disclaimer" FCC_disclaimer 3302,1970 r180 bottom
NT1 "Net-Tie" Net-Tie_50milWide_30milLong 3085,395 r180 top net-tie
Q1 "IPB180N08S402ATMA1" DDPAK-7 1390,1840 r0 top value=80V
Q2 "IPB180N08S402ATMA1" DDPAK-7 1390,1150 r0 top value=80V
Q3 "IPB180N08S402ATMA1" DDPAK-7 3010,1840 r0 top value=80V
Q4 "IPB180N08S402ATMA1" DDPAK-7 3010,1150 r0 top value=80V
Q5 "FDS2670" SOIC-8 3310,290 r90 top value=200V
Q6 "MMBT3904" SOT-23 160,670 r90 bottom value="40 V"
Q7 "MMBT3904" SOT-23 4260,635 r90 bottom value="40 V"
R1 "RT0603BRD0741K2L" 0603 1599,552 r180 top value=41.2k
R2 "RT0603BRD0741K2L" 0603 2645,575 r90 top value=41.2k
R3 "CRCW060310K0FKEA" 0603 1350,1580 r0 bottom value=10.0k
R4 "CRCW060310K0FKEA" 0603 2830,1570 r0 bottom value=10.0k
R5 "CRCW08055R11FKEA" 0805_HV 1270,1420 r0 bottom value=5.11
R6 "CRCW08055R11FKEA" 0805_HV 1160,940 r0 bottom value=5.11
R7 "CRCW08055R11FKEA" 0805_HV 2620,1050 r180 bottom value=5.11
R8 "CRCW08055R11FKEA" 0805_HV 2880,1295 r270 bottom value=5.11
R9 "RT0603BRD071K1L" 0603 1905,520 r90 bottom value=1.10k
R10 "RT0603BRD071K1L" 0603 2130,271 r180 top value=1.10k
R11 "CRCW060310K0FKEA" 0603 1140,795 r0 top value=10.0k
R12 "CRCW060310K0FKEA" 0603 2790,970 r270 bottom value=10.0k
R13 "Resistor" 2512 389,895 r0 top value=0.002
R14 "Resistor" 2512 3675,790 r0 top value=0.002
R15 "Resistor" 0603 1890,650 r270 top value=120
R16 "RC0603FR-07120KL" 0603 1170,670 r90 bottom value=120k
R17 "Resistor" 0603 1410,780 r270 bottom value=1.00k
R18 "Resistor" 0603 2980,780 r270 bottom value=1.00k
R19 "RC0603FR-07120KL" 0603 2730,660 r270 bottom value=120k
R20 "Resistor" 0603 1900,520 r90 top value=120
R21 "Resistor" 0603 1350,780 r270 bottom value=1.00k
R22 "Resistor" 0603 2920,780 r270 bottom value=1.00k
R23 "Resistor" 0603 1905,263 r270 bottom value=1.0k
R24 "Resistor" 0603 1905,390 r90 bottom value=1.0k
R25 "RC0603FR-07120KL" 0603 1530,630 r90 bottom value=120k
R26 "RC0603FR-07120KL" 0603 3100,780 r270 bottom value=120k
R28 "RT0603DRE072K03L" 0603 2261,272 r180 top value=2.03k
R29 "Resistor" 0603 2730,480 r270 bottom value=31.6k
R30 "Resistor" 0603 1370,370 r180 bottom value=31.6k
R32 "RC0603FR-073K74L" 0603 2261,327 r0 top value=3.74k
R33 "Resistor" 0805_HV 3790,485 r180 top value=90.9k
R34 "Resistor" 0603 2940,160 r0 top value=1.00k
R35 "Resistor" 0603 3780,140 r180 bottom value=15.0k
R36 "Resistor" 0603 3780,360 r180 bottom value=22.1k
R37 "Resistor" 0603 3470,360 r180 bottom value=22.1k
R38 "RT0603DRE071RL" 0603 2062,167 r90 bottom value=1.00
R39 "Resistor" 0603 3250,510 r180 top value=750
R40 "Resistor" 0603 2630,190 r180 bottom value=100
R41 "Resistor" 0603 3200,80 r180 top value=1.00k
R42 "CRCW06034K53FKEA" 0603 3780,70 r180 bottom value=4.53k
R43 "Resistor" 0603 3310,290 r0 bottom value=33.2
R44 "Resistor" 0805_HV 3370,80 r0 top value=3.01
R45 "CRCW06032K20JNEA" 0603 1870,670 r90 bottom value=2.2k
R46 "Resistor" 0603 1100,310 r0 bottom value=100
R47 "Resistor" 0603 1100,110 r0 bottom value=100
R48 "CRCW060310K0FKEA" 0603 1490,320 r180 bottom value=10.0k
R49 "Resistor" 0603 290,700 r180 bottom value=1.00k
R50 "Resistor" 0603 4070,740 r0 bottom value=1.00k
R51 "Resistor" 0603 1490,260 r0 bottom value=100
R52 "CRCW06033K16FKEA" 0603 290,560 r180 bottom value=3.16k
R53 "CRCW06033K16FKEA" 0603 4135,660 r0 bottom value=3.16k
R54 "CRCW060310K0FKEA" 0603 160,560 r0 bottom value=10.0k
R55 "CRCW060310K0FKEA" 0603 4135,570 r180 bottom value=10.0k
R56 "CRCW06032K20JNEA" 0603 2158,165 r270 bottom value=2.2k
R57 "CRCW06032K20JNEA" 0603 2256,110 r90 bottom value=2.2k
R58 "CRCW0603200KJNEA" 0603 3910,370 r180 bottom value=200k
R59 "CRCW0603200KJNEA" 0603 4300,460 r180 top value=200k
R60 "CRM2010-JW-3R3ELF" 2010 1690,920 r90 bottom value=3.3
R61 "CRM2010-JW-3R3ELF" 2010 3295,1025 r90 bottom value=3.3
S1 "G12AP" SW_G1xAP 1570,110 r180 top
S2 "SKRKAEE010" SW_SKRKAEE010 1880,120 r90 top
S3 "SKRKAEE010" SW_SKRKAEE010 2070,120 r90 top
S4 "SKRKAEE010" SW_SKRKAEE010 2250,120 r90 top
T1 "XFMR_031-00019" XFMR_031-00019 3720,240 r0 top value=540uH
TP1 "5012" Keystone5012 160,1710 r0 top
TP2 "5012" Keystone5012 1800,2100 r0 top
TP3 "5012" Keystone5012 3330,2120 r0 top
TP4 "5012" Keystone5012 4240,1710 r0 top
TP7 "5012" Keystone5012 2500,2100 r0 top
TP8 "5012" Keystone5012 2690,2100 r0 top
TP9 "5012" Keystone5012 1090,2110 r0 top
TP10 "5012" Keystone5012 580,2110 r0 top
TP11 "5011" Keystone5011 4240,1050 r0 top
TP12 "5011" Keystone5011 160,1040 r0 top
TP13 "5011" Keystone5011 920,620 r0 top
TP16 "5012" Keystone5012 610,620 r0 top
TP17 "5012" Keystone5012 4240,865 r0 top
TP19 "5011" Keystone5011 3116,613 r0 top
U1 "UCC27211ADRMR" DRM0008A 980,1270 r180 bottom
U2 "OPA2211AIDDA" DDA0008C_M 1380,560 r270 bottom
U3 "OPA2211AIDDA" DDA0008C_M 2940,560 r270 bottom
U4 "UCC27211ADRMR" DRM0008A 2620,1270 r180 bottom
U5 "TLV1117-33IDCY" DCY0004A_N 3013,250 r180 bottom
U6 "UCC3813D-1" D0008A_N 3550,210 r180 bottom
U7 "UCD3138RJAT" RJA0040A 2170,570 r0 bottom
ZZ2 "These assemblies are ESD sensitive, ESD precautions shall be observed." AssemblyNote 185,3829.11 r0 top
ZZ3 "These assemblies must be clean and free from flux and all contaminants. Use of no clean flux is not acceptable." AssemblyNote 185,3740.56 r0 top
ZZ4 "These assemblies must comply with workmanship standards IPC-A-610 Class 2, unless otherwise specified." AssemblyNote 185,3652 r0 top

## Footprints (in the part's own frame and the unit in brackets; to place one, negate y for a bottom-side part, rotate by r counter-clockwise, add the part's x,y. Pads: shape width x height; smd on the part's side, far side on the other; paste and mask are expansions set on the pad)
0402 [mm] "0402 from SM-752 data"
  rect 0.8x0.6 smd: 1(-0.6,0) 2(0.6,0)
  silkscreen extent -1.22,-0.52 1.22,0.52, body extent -0.55,-0.3 0.55,0.3, height 0.6
0603 [mm] "0603 from SM-752 data"
  rect 1x0.95 smd: 1(-0.8,0) 2(0.8,0)
  silkscreen extent -1.52,-0.69 1.52,0.69, body extent -0.87,-0.47 0.87,0.47, height 1
0805_HV [mil] "0805 with 30mil clearance between pads"
  rect 50x63 smd: 1(-40,0) 2(40,0)
  silkscreen extent -74,-40 74,40, body extent -43,-29 43,29, height 57
1206 [mm] "1206 from SM-752 data"
  rect 1.3x1.85 smd: 1(-1.45,0) 2(1.45,0)
  silkscreen extent -2.4,-1.21 2.4,1.21, body extent -1.7,-0.9 1.7,0.9, height 1.35
1206_180 [mm] "1206_180"
  rect 1.1x1.6 smd: 1(-1.7,0) 2(1.7,0)
  silkscreen extent -0.9,-1 0.9,1, body extent -1.75,-0.95 1.75,0.95, height 1.8
1210_220 [mm] "1210"
  rect 1.3x2.7 smd: 1(-1.45,0) 2(1.45,0)
  silkscreen extent -2.32,-1.57 2.32,1.57, body extent -1.7,-1.35 1.7,1.35, height 2.2
1210_270 [mm] "1210"
  rect 1.3x2.7 smd: 1(-1.45,0) 2(1.45,0)
  silkscreen extent -2.32,-1.57 2.32,1.57, body extent -1.7,-1.35 1.7,1.35, height 2.7
2010 [mm] "Chip Capacitor, Body 5.08x2.54mm, IPC Medium Density"
  rect 1.6x2.7 smd: 1(-2.3,0) 2(2.3,0)
  silkscreen extent -3.42,-1.65 3.42,1.65, body extent -2.73,-1.45 2.73,1.45, height 1.66
2220_280 [mm] "Chip Capacitor, Body 5.7x5.0mm, IPC Medium Density"
  rect 1.6x5.3 smd: 1(-2.6,0) 2(2.6,0)
  silkscreen extent -3.69,-2.94 3.69,2.94, body extent -2.95,-2.62 2.95,2.62, height 2.8
2512 [mm] "Chip Resistor, Body 6.3x3.2mm, IPC Medium Density"
  rect 1.3x3.4 smd: 1(-2.95,0) 2(2.95,0)
  silkscreen extent -1.9,-1.6 1.9,1.6, body extent -3.22,-1.67 3.22,1.67, height 0.71
AssemblyNote [mil] "Assembly Note"
CAPSMT_62_KE0 [mm] "12.5 x 13.5mm:  Chemi-Con KE0"
  rect 5.7x2.5 smd: 1(-4.85,0) 2(4.85,0)
  silkscreen extent -6.6,-6.6 6.6,6.6, body extent -6.6,-6.6 6.6,6.6, height 14
CONN_5103308-1 [mm] "TE Connectivity (AMP) Rev E datasheet"
  rect 1.65x1.65 hole 1.016 mask+0: 1(-5.08,-1.27)
  round 1.65 hole 1.016 mask+0: 2(-5.08,1.27) 3(-2.54,-1.27) 4(-2.54,1.27) 5(0,-1.27) 6(0,1.27) 7(2.54,-1.27) 8(2.54,1.27) 9(5.08,-1.27) 10(5.08,1.27)
  silkscreen extent -10.16,-5.33 10.16,4.57, body extent -10.16,-4.57 10.16,4.57, height 9.87
D0008A_N [mm] "SOIC, 8-Leads, Body 4.9x3.9mm, Pitch 1.27mm, IPC Medium Density"
  oval 1.45x0.6 smd: 1(-2.725,1.905) 2(-2.725,0.635) 3(-2.725,-0.635) 4(-2.725,-1.905) 5(2.725,-1.905) 6(2.725,-0.635) 7(2.725,0.635) 8(2.725,1.905)
  silkscreen extent -3.3,-2.5 0.9,2.5, body extent -3,-2.45 3,2.45, height 1.63
DCY0004A_N [mm] "SOT223/SC73, 4-Leads, Body 6.5x3.5mm, Pitch 2.3mm, Lead Span 7mm, IPC Medium Density"
  rrect11% 1.75x0.9 smd: 1(-3.125,2.3) 2(-3.125,0) 3(-3.125,-2.3)
  rrect6% 1.75x3.2 smd: 4(3.125,0)
  silkscreen extent -3.03,-3.35 1.4,3.47, body extent -3.48,-3.25 3.48,3.25, height 1.68
DDA0008C_M [mm] "SOIC, 8-Leads, Body 4.9x3.9mm, Pitch 1.27mm, Exposed Pad, IPC Low Density"
  rrect100% 1.65x0.65 smd: 1(-2.825,1.905) 2(-2.825,0.635) 3(-2.825,-0.635) 4(-2.825,-1.905) 5(2.825,-1.905) 6(2.825,-0.635) 7(2.825,0.635) 8(2.825,1.905)
  rrect4% 2.95x4.9 smd paste-1.5 mask-1.5: 9(0,0)
  rrect4% 2.49x3 on Bottom Paste: 9(0,0)
  rrect4% 2.49x3 on Bottom Solder: 9(0,0)
  silkscreen extent -3.35,-2.5 1.07,2.58, body extent -3.01,-2.45 3.01,2.45, height 1.7
DDPAK-7 [mil]
  rect 38x138 smd: 1(-150,-347) 2(-100,-347) 3(-50,-347) 5(50,-347) 6(100,-347) 7(150,-347)
  rect 420x458 smd: 4(0,6)
  silkscreen extent -168,-264 168,-247, body extent -210,-386 210,240, height 190
DRM0008A [mm] "TI"
  oval 0.6x0.3 smd: 1(-1.9,1.2) 2(-1.9,0.4) 3(-1.9,-0.4) 4(-1.9,-1.2) 5(1.9,-1.2) 6(1.9,-0.4) 7(1.9,0.4) 8(1.9,1.2)
  rect 2.45x3.38 smd paste-1.25: 9(0,0)
  silkscreen extent -2.2,-2.2 2.2,2.2, body extent -2.05,-2.05 2.05,2.05, height 1.01
FCC_disclaimer [mil]
Fiducial10-20 [mm]
  round 1 smd mask+0.5: 1(0,0)
  Top Layer keep-out circle w1.178: c0,0 r0.5
FUSE_SSQ [mm] "Bel Fuse"
  rect 2x3.18 smd: 1(-2.5,0) 2(2.5,0)
  silkscreen extent -1.27,-1.32 1.27,1.32, body extent -3.17,-1.32 3.17,1.32, height 2.64
Keystone5011 [mil] "Keystone Multipurpose loops"
  round 87 hole 63: 1(0,0)
  silkscreen extent -70,-70 70,70, body extent -63,-63 63,62, height 319
Keystone5012 [mil] "Keystone Multipurpose loops"
  round 87 hole 63: 1(0,0)
  silkscreen extent -70,-70 70,70, body extent -63,-63 63,62, height 319
Keystone_1902C [mil] "Hex Standoff, 4-40 threaded, nylon"
  round 1 on Mech4: 0(0,0)
  body extent -145,-126 146,126, height 501
LED_LTST-C190 [mm] "Lite-On"
  rect 0.8x0.8 smd: 1(-0.75,0) 2(0.75,0)
  silkscreen extent -1.1,-0.8 1.8,0.8, body extent -0.85,-0.45 0.85,0.45, height 0.9
Net-Tie_50milWide_30milLong [mil] "50mil net tie, no solder mask opening, no solder paste"
  rect 30x50 on Mid1 paste-20 mask-20: 1(-15,0) 2(15,0)
"NY PMS 440 0025 PH" [mm] "4-40 nylon screw and mounting hole"
  round 8 hole 3.2: 1(0,0)
  body extent -3.3,-3.3 3.3,3.3, height 2.69
On-Shore_ED120_2DS [mm] "ONSHORE"
  rrect5% 2x2 hole 1.25: 1(-2.54,0)
  round 2 hole 1.25: 2(2.54,0)
  silkscreen extent -5.6,-4 5.12,5, body extent -5.78,-4 5.08,5, height 13
RJA0040A [mm] "VQFN-40"
  rrect42% 0.6x0.24 smd: 1(-2.9,2.25) 2(-2.9,1.75) 3(-2.9,1.25) 4(-2.9,0.75) 5(-2.9,0.25) 6(-2.9,-0.25) 7(-2.9,-0.75) 8(-2.9,-1.25) 9(-2.9,-1.75) 10(-2.9,-2.25) 21(2.9,-2.25) 22(2.9,-1.75) 23(2.9,-1.25) 24(2.9,-0.75) 25(2.9,-0.25) 26(2.9,0.25) 27(2.9,0.75) 28(2.9,1.25) 29(2.9,1.75) 30(2.9,2.25)
  rrect42% 0.24x0.6 smd: 11(-2.25,-2.9) 12(-1.75,-2.9) 13(-1.25,-2.9) 14(-0.75,-2.9) 15(-0.25,-2.9) 16(0.25,-2.9) 17(0.75,-2.9) 18(1.25,-2.9) 19(1.75,-2.9) 20(2.25,-2.9) 31(2.25,2.9) 32(1.75,2.9) 33(1.25,2.9) 34(0.75,2.9) 35(0.25,2.9) 36(-0.25,2.9) 37(-0.75,2.9) 38(-1.25,2.9) 39(-1.75,2.9) 40(-2.25,2.9)
  rrect9% 1.17x1.17 on Bottom Paste: 41(-1.37,-1.37) 41(-1.37,0) 41(-1.37,1.37) 41(0,-1.37) 41(0,0) 41(0,1.37) 41(1.37,-1.37) 41(1.37,0) 41(1.37,1.37)
  rrect2% 4.15x4.15 smd paste-4.15: 41(0,0)
  rrect31% 0.32x0.32 smd: A1(-2.74,2.74) A2(-2.74,-2.74) A3(2.74,-2.74) A4(2.74,2.74)
  silkscreen extent -3.22,-3.22 3.22,3.22, body extent -3,-3 3,3, height 1
Samtec_HTSW-102-09-x-S [mm] "Header, 2x1, 2.54mm, TH"
  rect 1.55x1.55 hole 1.02: 1(-1.27,0)
  round 1.55 hole 1.02: 2(1.27,0)
  silkscreen extent -2.54,-1.24 2.54,1.6, body extent -2.54,-1.24 2.54,1.24, height 8.38
Samtec_HTSW-105-07-G-S [mm] "Samtec 100mil, 1x5, 230 mil above insulator"
  rrect6% 1.65x1.65 hole 1.016: 1(-5.08,0)
  round 1.65 hole 1.016: 2(-2.54,0) 3(0,0) 4(2.54,0) 5(5.08,0)
  silkscreen extent -7.11,-1.27 6.35,1.27, body extent -6.35,-1.27 6.35,1.27, height 8.38
SER2918H [mm] "COILCRAFT"
  rect 5.59x5.33 smd: 1(-14.355,5.075) 2(-14.455,-5.075)
  rect 6.35x5.28 smd: 3(8.25,0)
  silkscreen extent -11.04,-14 10.81,13.9, body extent -16.7,-14.05 11.22,13.85, height 17.82
SOD-123 [mm] "On Semi recommended land pattern"
  rect 0.915x1.22 smd: 1(-1.637,0) 2(1.637,0)
  silkscreen extent -2.74,-1.17 2.03,1.17, body extent -1.93,-0.9 1.93,0.9, height 1.35
SOD-123FL [mm] "Copied from SOD-123"
  rect 0.915x1.22 smd: 1(-1.637,0) 2(1.637,0)
  silkscreen extent -2.74,-1.16 1.68,1.16, body extent -1.9,-0.9 1.9,0.9, height 1
SOD-123W [mm] "NXP recommended land pattern"
  rect 1.2x1.2 smd paste-0.05: 1(-1.4,0) 2(1.4,0)
  silkscreen extent -2.64,-1.14 1.68,1.14, body extent -1.85,-0.95 1.85,0.95, height 1.1
SOIC-8 [mm] "duplicate of SO-8.  SOIC, 8-Leads, Body 5.0x4.0mm (max), Pitch 1.27mm, IPC Medium Density"
  rrect17% 1.45x0.6 smd: 1(-2.725,1.905) 2(-2.725,0.635) 3(-2.725,-0.635) 4(-2.725,-1.905) 5(2.725,-1.905) 6(2.725,-0.635) 7(2.725,0.635) 8(2.725,1.905)
  silkscreen extent -3.5,-2.5 0.9,2.5, body extent -3,-2.45 3,2.45, height 1.63
SOT-23 [mm] "SOT23, 3-Leads, Body 2.9x1.3mm, Pitch 0.95mm, Lead Span 2.5mm, IPC Medium Density"
  rrect50% 1x0.6 smd: 1(-1.2,0.95) 2(-1.2,-0.95) 3(1.2,0)
  silkscreen extent -1.63,-1.5 0.7,1.5, body extent -1.16,-1.45 1.21,1.45, height 1
SOT-23L [mm] "SOT23, 3-Leads, Body 2.9x1.3mm, Pitch 0.95mm, Lead Span 2.5mm, IPC High Density"
  rrect50% 0.8x0.6 smd: 1(-1.1,0.95) 2(-1.1,-0.95) 3(1.1,0)
  silkscreen extent -1.5,-1.5 0.7,1.5, body extent -1.16,-1.45 1.21,1.45, height 1
SW_G1xAP [mil] "Switch, NKK G Series"
  round 50 hole 26: 1(-100,50) 3(100,50) 4(-100,-50) 5(0,-50) 6(100,-50)
  silkscreen extent -138,-88 138,89, body extent -138,-88 138,89, height 424
SW_SKRKAEE010 [mm] "Alps recommended land pattern"
  rect 0.8x2 smd: 1(-2.1,0) 2(2.1,0)
  silkscreen extent -1.9,-1.44 1.92,1.44, body extent -2.4,-1.45 2.4,1.45, height 1.96
XFMR_031-00019 [mil] "SMD, 8-Leads, Body 400x300mil, Pitch 79mil"
  rect 63x50 smd: 1(-201.5,118.5) 2(-201.5,39.5) 3(-201.5,-39.5) 4(-201.5,-118.5) 5(201.5,-118.5) 6(201.5,-39.5) 7(201.5,39.5) 8(201.5,118.5)
  silkscreen extent -199,-180 150,180, body extent -217,-200 216,200, height 220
